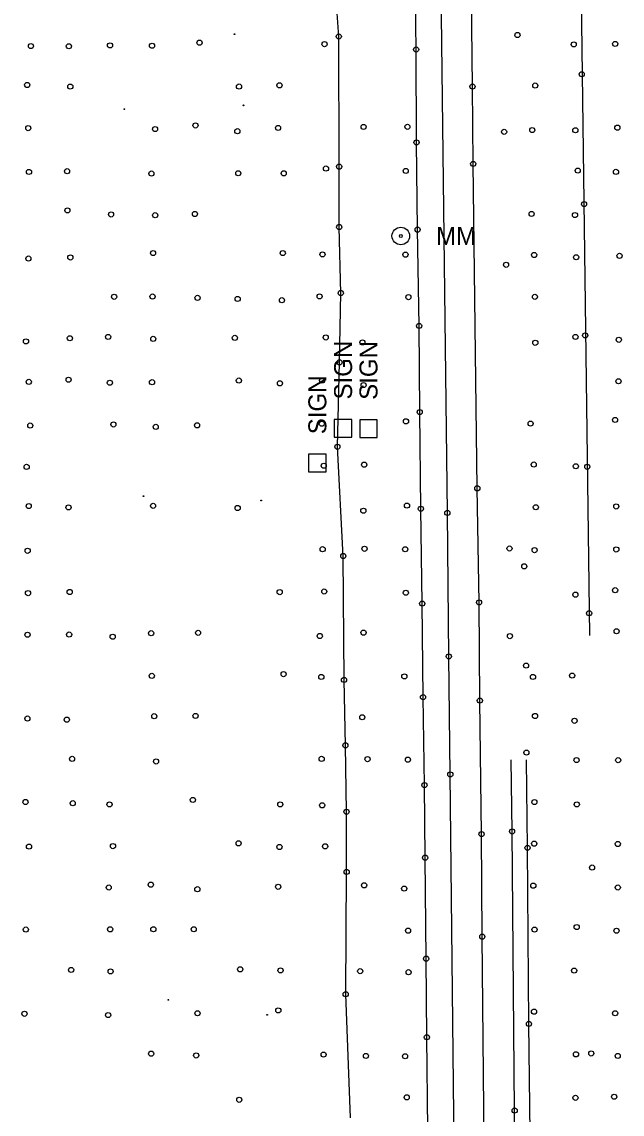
# Model space of a CAD drawing. Extents: x 20503438 to 20508873, y 7964251 to 7984667.
# Drawn here: x 20505218.4 to 20505451.9, y 7981861 to 7982286.2 of the extents above; entities that cross this region are included whole.
import ezdxf

# ---------------------------------------------------------------- set-up
doc = ezdxf.new("R2010")
doc.units = 0
for name, color, linetype in [('SurBreakLine', 7, 'Continuous'), ('SurControl', 7, 'Continuous'), ('SurDrainageArrowDown', 7, 'Continuous'), ('SurDrainageArrowUp', 7, 'Continuous'), ('SurEdgeRoadPaved', 7, 'Continuous'), ('SurEdgeShoulderPaved', 7, 'Continuous'), ('SurRoadPoints', 7, 'Continuous'), ('SurSurveyPoints', 7, 'Continuous')]:
    doc.layers.add(name, color=color, linetype=linetype)

msp = doc.modelspace()

# ---------------------------------------------------------------- linework, layer by layer
at = {"layer": 'SurBreakLine'}
msp.add_lwpolyline([(20505398.64, 7981809.84), (20505397.46, 7981930.08), (20505397.17, 7981970), (20505396.52, 7982021.97), (20505396.21, 7982060.19), (20505395.53, 7982104.61), (20505393.93, 7982230.88), (20505393.64, 7982260.99), (20505392.31, 7982377.38), (20505390.8, 7982544.69), (20505390.42, 7982583.24), (20505388.95, 7982707.76), (20505388.09, 7982786.72), (20505387.46, 7982826.69)], dxfattribs=at)
at = {"layer": 'SurControl'}
for centre in [(20505301.11, 7982281.41), (20505258.2, 7982252.19), (20505304.58, 7982253.68), (20505265.69, 7982101.54), (20505311.43, 7982099.89), (20505275.33, 7981905.44), (20505313.81, 7981899.65)]:
    msp.add_circle(centre, 0.15, dxfattribs=at)
at = {"layer": 'SurDrainageArrowDown'}
msp.add_lwpolyline([(20505346.18, 7981859.59), (20505344.33, 7981907.65), (20505344.7, 7981955.29), (20505344.64, 7981978.69), (20505344.21, 7982004.54), (20505343.68, 7982030), (20505343.38, 7982078.25), (20505341.11, 7982120.78), (20505341.93, 7982153.66), (20505342.43, 7982180.64), (20505341.8, 7982206.33), (20505341.77, 7982229.83), (20505341.65, 7982280.49), (20505338.19, 7982329.69)], dxfattribs=at)
at = {"layer": 'SurDrainageArrowUp'}
msp.add_line((20505434.51, 7982413.05), (20505439.13, 7982047.34), dxfattribs=at)
at = {"layer": 'SurEdgeRoadPaved'}
for points in [[(20505388.35, 7981679.93), (20505385.03, 7981993.21), (20505384.45, 7982039.17), (20505383.88, 7982095.02), (20505381.48, 7982299.61), (20505380.65, 7982383.29), (20505379.4, 7982506.12), (20505379.18, 7982540.54), (20505378.75, 7982564.52), (20505377.74, 7982654.37), (20505376.87, 7982720.03), (20505375.97, 7982814.93)], [(20505420.77, 7980848.98), (20505419.47, 7980988.86), (20505418.51, 7981057.7), (20505417.69, 7981158.74), (20505416.9, 7981224.3), (20505416.49, 7981269.61), (20505416.17, 7981298.98), (20505414.84, 7981406.19), (20505414.3, 7981473.72), (20505412.74, 7981608.4), (20505412.1, 7981681.06), (20505410.05, 7981862.37), (20505409.06, 7981971.02), (20505408.76, 7981998.85)]]:
    msp.add_lwpolyline(points, dxfattribs=at)
at = {"layer": 'SurEdgeShoulderPaved'}
for points in [[(20505376.33, 7981854.83), (20505375.9, 7981890.93), (20505375.62, 7981921.5), (20505375.22, 7981960.81), (20505374.97, 7981989.08), (20505374.41, 7982023.3), (20505374.1, 7982059.76), (20505373.58, 7982096.65), (20505373.13, 7982134.3), (20505372.89, 7982167.83), (20505372.29, 7982205.3), (20505371.89, 7982239.27), (20505371.72, 7982275.43), (20505370.69, 7982352.42), (20505370.32, 7982389.99), (20505369.91, 7982434.24), (20505369.5, 7982468.48), (20505369.07, 7982503.94), (20505368.59, 7982575.12), (20505368.11, 7982610.58), (20505367.94, 7982647.52), (20505366.98, 7982718.13), (20505365.41, 7982861.87)], [(20505426.86, 7980832.89), (20505425.41, 7980977.21), (20505425.21, 7981009.67), (20505424.56, 7981059.21), (20505424.03, 7981108.16), (20505423.08, 7981188.71), (20505422.39, 7981257.33), (20505421.78, 7981317.16), (20505420.57, 7981436.1), (20505420.04, 7981471), (20505419.87, 7981506.55), (20505419.47, 7981534.86), (20505418.94, 7981582.14), (20505418.66, 7981615.83), (20505418.01, 7981655.29), (20505417.66, 7981685.28), (20505416.92, 7981789.53), (20505415.62, 7981896.09), (20505415.07, 7981964.65), (20505414.65, 7981998.91)]]:
    msp.add_lwpolyline(points, dxfattribs=at)
at = {"layer": 'SurRoadPoints'}
for points in [[(20505346.74, 7982127.98), (20505346.74, 7982127.98), (20505346.74, 7982131.41), (20505339.88, 7982131.41), (20505339.88, 7982124.55), (20505346.74, 7982124.55), (20505346.74, 7982127.98)], [(20505356.63, 7982127.84), (20505356.63, 7982127.84), (20505356.63, 7982131.27), (20505349.77, 7982131.27), (20505349.77, 7982124.41), (20505356.63, 7982124.41), (20505356.63, 7982127.84)], [(20505336.73, 7982114.45), (20505336.73, 7982114.45), (20505336.73, 7982117.88), (20505329.87, 7982117.88), (20505329.87, 7982111.02), (20505336.73, 7982111.02), (20505336.73, 7982114.45)]]:
    msp.add_lwpolyline(points, dxfattribs=at)
for radius in [3.43, 0.571]:
    msp.add_circle((20505365.77, 7982202.84), radius, dxfattribs=at)
at = {"layer": 'SurSurveyPoints'}
for centre in [(20505341.65, 7982280.49), (20505411.15, 7982281.07), (20505221.88, 7982276.78), (20505236.64, 7982276.68), (20505252.65, 7982277.03), (20505268.98, 7982276.91), (20505287.48, 7982278.08), (20505336.1, 7982277.52), (20505371.72, 7982275.43), (20505433.03, 7982277.41), (20505449.17, 7982277.59), (20505436.15, 7982265.79), (20505220.44, 7982261.62), (20505237.2, 7982260.99), (20505302.83, 7982261.02), (20505318.57, 7982261.49), (20505393.64, 7982260.99), (20505418.08, 7982261.41), (20505285.9, 7982245.86), (20505351.3, 7982245.29), (20505368.33, 7982245.33), (20505220.84, 7982244.83), (20505270.16, 7982244.45), (20505302.18, 7982243.63), (20505318.03, 7982244.91), (20505405.97, 7982243.38), (20505416.9, 7982244.06), (20505433.67, 7982243.99), (20505450.01, 7982245), (20505371.89, 7982239.27), (20505336.66, 7982229.09), (20505341.77, 7982229.83), (20505393.93, 7982230.88), (20505434.6, 7982228.3), (20505221.12, 7982227.78), (20505235.94, 7982228.05), (20505268.74, 7982227.14), (20505302.54, 7982227.25), (20505320.23, 7982227.22), (20505367.69, 7982228.17), (20505449.48, 7982227.8), (20505236.06, 7982212.79), (20505285.69, 7982211.4), (20505416.65, 7982211.41), (20505437.05, 7982215.26), (20505253.05, 7982211.21), (20505270.23, 7982210.93), (20505433.53, 7982210.99), (20505341.8, 7982206.33), (20505372.29, 7982205.3), (20505237.22, 7982194.47), (20505269.4, 7982196.19), (20505319.86, 7982196.19), (20505335.3, 7982195.68), (20505367.57, 7982195.57), (20505417.63, 7982195.44), (20505433.98, 7982194.54), (20505450.87, 7982195.09), (20505220.9, 7982194.05), (20505406.71, 7982191.62), (20505254.25, 7982179.17), (20505269.19, 7982179.26), (20505286.7, 7982178.74), (20505302.3, 7982178.33), (20505319.53, 7982177.83), (20505334.17, 7982179.32), (20505342.43, 7982180.64), (20505368.72, 7982179.03), (20505417.95, 7982179.15), (20505372.89, 7982167.83), (20505219.96, 7982161.8), (20505237.02, 7982163.01), (20505251.9, 7982163.53), (20505269.47, 7982162.79), (20505301.21, 7982163.17), (20505336.57, 7982163.34), (20505350.83, 7982161.4), (20505418.09, 7982161.26), (20505433.72, 7982163.55), (20505437.5, 7982164.14), (20505450.56, 7982162.42), (20505341.93, 7982153.66), (20505221.04, 7982146.04), (20505236.54, 7982146.88), (20505252.58, 7982145.71), (20505268.99, 7982145.91), (20505302.77, 7982146.56), (20505318.75, 7982145.48), (20505335.13, 7982146.54), (20505351.29, 7982144.79), (20505450.45, 7982146.28), (20505367.78, 7982130.67), (20505373.13, 7982134.3), (20505449.12, 7982131.23), (20505221.61, 7982129.04), (20505253.96, 7982129.47), (20505270.43, 7982128.52), (20505286.52, 7982129.13), (20505335.05, 7982129.75), (20505416.26, 7982129.81), (20505341.11, 7982120.78), (20505351.54, 7982113.81), (20505417.47, 7982113.86), (20505220.21, 7982112.96), (20505335.79, 7982113.41), (20505433.85, 7982113.19), (20505438.3, 7982112.99), (20505395.53, 7982104.61), (20505221.02, 7982097.7), (20505236.52, 7982097.19), (20505269.39, 7982097.79), (20505302.3, 7982096.94), (20505368.17, 7982097.87), (20505373.58, 7982096.65), (20505418.3, 7982097.22), (20505449.58, 7982097.55), (20505351.2, 7982095.87), (20505383.88, 7982095.02), (20505220.6, 7982080.29), (20505335.36, 7982080.9), (20505351.65, 7982081.06), (20505367.49, 7982080.89), (20505408.05, 7982081.18), (20505417.82, 7982080.54), (20505449.6, 7982080.81), (20505343.38, 7982078.25), (20505413.8, 7982074.23), (20505220.75, 7982063.8), (20505236.95, 7982064.24), (20505318.65, 7982064.19), (20505335.99, 7982064.44), (20505367.72, 7982063.96), (20505433.68, 7982063.2), (20505449.13, 7982064.95), (20505374.1, 7982059.76), (20505396.21, 7982060.19), (20505439.02, 7982055.99), (20505220.57, 7982047.6), (20505236.74, 7982047.69), (20505253.68, 7982046.82), (20505268.63, 7982048.21), (20505286.9, 7982048.35), (20505334.24, 7982047.11), (20505351.27, 7982048.42), (20505408.23, 7982047.07), (20505449.71, 7982048.96), (20505384.45, 7982039.17), (20505414.49, 7982035.58), (20505268.9, 7982031.59), (20505320.17, 7982032.28), (20505334.84, 7982031.19), (20505343.68, 7982030), (20505367.15, 7982031.38), (20505417.18, 7982031.18), (20505432.41, 7982031.69), (20505374.41, 7982023.3), (20505396.52, 7982021.97), (20505269.86, 7982015.89), (20505285.91, 7982016), (20505417.98, 7982015.96), (20505220.5, 7982014.98), (20505235.83, 7982014.54), (20505350.77, 7982015.48), (20505433.35, 7982014.1), (20505344.21, 7982004.54), (20505237.87, 7981999.28), (20505334.97, 7981999.28), (20505352.82, 7981999.18), (20505368.55, 7981998.96), (20505414.62, 7982001.73), (20505434.13, 7981998.83), (20505450.34, 7981998.78), (20505270.56, 7981998.28), (20505385.03, 7981993.21), (20505374.97, 7981989.08), (20505219.77, 7981982.49), (20505238.14, 7981982.03), (20505284.87, 7981983.29), (20505417.74, 7981982.46), (20505252.47, 7981981.57), (20505318.88, 7981981.55), (20505335.18, 7981981.2), (20505344.64, 7981978.69), (20505434.23, 7981981.57), (20505397.17, 7981970), (20505409.06, 7981971.02), (20505221.13, 7981965.14), (20505253.8, 7981965.32), (20505302.66, 7981966.41), (20505318.56, 7981964.98), (20505336.33, 7981965.23), (20505415.07, 7981964.65), (20505417.66, 7981966.28), (20505450.2, 7981966.15), (20505375.22, 7981960.81), (20505440.18, 7981956.98), (20505344.7, 7981955.29), (20505252.15, 7981949.21), (20505268.5, 7981950.31), (20505286.62, 7981948.54), (20505318.08, 7981949.49), (20505351.5, 7981950.06), (20505367.1, 7981948.78), (20505417.31, 7981949.93), (20505450.17, 7981949.21), (20505219.89, 7981932.84), (20505252.68, 7981932.93), (20505269.5, 7981932.95), (20505285.22, 7981932.94), (20505368.58, 7981932.41), (20505417.8, 7981932.82), (20505434.19, 7981933.8), (20505449.68, 7981932.37), (20505397.46, 7981930.08), (20505375.62, 7981921.5), (20505237.52, 7981917.13), (20505252.87, 7981916.56), (20505303.3, 7981917.36), (20505318.98, 7981916.93), (20505349.98, 7981916.64), (20505368.79, 7981916.24), (20505433.2, 7981916.86), (20505344.33, 7981907.65), (20505318.12, 7981901.37), (20505417.59, 7981900.88), (20505219.35, 7981900.04), (20505251.91, 7981899.55), (20505286.68, 7981900.26), (20505449.13, 7981900.25), (20505415.62, 7981896.09), (20505375.9, 7981890.93), (20505268.65, 7981884.52), (20505286.18, 7981883.83), (20505335.73, 7981884.16), (20505433.91, 7981884.27), (20505439.86, 7981884.6), (20505352.19, 7981883.65), (20505367.42, 7981883.51), (20505450.15, 7981883.65), (20505368.08, 7981867.52), (20505433.71, 7981867.33), (20505448.78, 7981867.76), (20505302.93, 7981866.56), (20505410.05, 7981862.37)]:
    msp.add_circle(centre, 1, dxfattribs=at)

# ---------------------------------------------------------------- texts
at = {"layer": 'SurRoadPoints'}
for s, rotation, p in [('MM', 360, (20505379.48, 7982199.35)), ('SIGN', 90, (20505346.81, 7982139.19)), ('SIGN', 90, (20505356.7, 7982139.05)), ('SIGN', 90, (20505336.8, 7982125.66))]:
    msp.add_text(s, height=6.995, rotation=rotation, dxfattribs=at).set_placement(p)

doc.saveas('drawing.dxf')
